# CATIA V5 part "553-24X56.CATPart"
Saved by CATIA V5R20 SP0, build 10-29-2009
Part number: 553-24X56
Definition: NONE
Nomenclature: 553-24X56
Source: Unknown
Description: 553-24X56
Bounding box of the stored display mesh (mm): x 0 to 56, y -17.5 to 17.5, z -17.5 to 17.5
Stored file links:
  C:\Users\Utente\Desktop\IO LAVORO\3D X SITO CF\X SITO\PLASTICA\553\553-24X56.CATPart
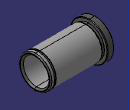
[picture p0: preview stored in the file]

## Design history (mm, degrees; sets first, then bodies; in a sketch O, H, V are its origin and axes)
Body1 "553-24X56" (main body)
  Solid1: solid without history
